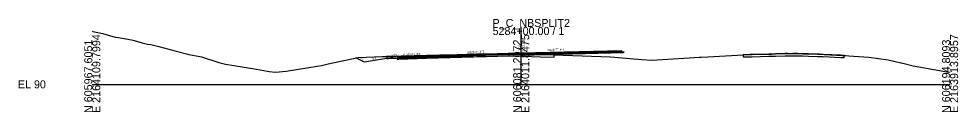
# Model space of a CAD drawing. Extents: x -26 to 1303, y -10 to 12038.
# Drawn here: x -25.7 to 302.8, y 2490.3 to 2522.8 of the extents above; entities that cross this region are included whole.
import ezdxf

# ---------------------------------------------------------------- set-up
doc = ezdxf.new("R2010")
doc.units = 0
for name, color, linetype in [('RD_GPK_XS_Cell', 7, 'Continuous'), ('RD_XS_Base', 7, 'Continuous'), ('RD_XS_ExGround', 7, 'Continuous'), ('RD_XS_ExPaveRet', 7, 'Continuous'), ('RD_XS_Greenside', 7, 'Continuous'), ('RD_XS_Pave', 7, 'Continuous'), ('RD_XS_PaveOvlay_CP', 7, 'Continuous'), ('RD_XS_TieSlope', 7, 'Continuous'), ('RD_XS_TX_Elev_EX', 7, 'Continuous'), ('RD_XS_TX_Elev_PR', 7, 'Continuous'), ('RD_XS_TX_ShdSlope', 7, 'Continuous'), ('RD_XS_TX_Slope', 7, 'Continuous')]:
    doc.layers.add(name, color=color, linetype=linetype)

msp = doc.modelspace()

# ---------------------------------------------------------------- linework, layer by layer
at = {"layer": 'RD_GPK_XS_Cell'}
for p, q in [((150, 2500), (150, 2520)), ((0, 2500), (150, 2500)), ((150, 2500), (300, 2500))]:
    msp.add_line(p, q, dxfattribs=at)
at = {"layer": 'RD_XS_Base'}
for p, q in [((150, 2510.51), (116.74, 2509.64)), ((116.74, 2509.14), (150, 2510.01)), ((138, 2510.2), (138, 2510.2)), ((150, 2510.51), (185.75, 2511.44)), ((185.75, 2510.94), (150, 2510.01)), ((150, 2510.01), (150, 2510.67)), ((150, 2510.67), (150, 2510.67)), ((150, 2510.67), (150, 2510.67)), ((150, 2510.67), (150, 2510.51)), ((150, 2510.51), (150, 2510.51)), ((150, 2510.01), (150, 2510.51)), ((150, 2510.51), (150, 2510.51)), ((150, 2510.51), (150, 2510.51)), ((150, 2510.01), (150, 2510.01)), ((174, 2511.13), (174, 2511.13)), ((174, 2511.13), (174, 2511.13)), ((174, 2510.63), (174, 2510.63)), ((174, 2510.63), (174, 2510.63)), ((185.25, 2511.43), (185.25, 2511.43)), ((185.75, 2511.44), (185.75, 2510.94)), ((185.75, 2511.41), (185.75, 2511.41)), ((107.17, 2509.26), (106.67, 2509.24)), ((106.67, 2509.24), (106.67, 2509.24)), ((106.67, 2509.24), (106.67, 2508.74)), ((106.67, 2508.74), (107.17, 2508.76)), ((116.74, 2509.64), (107.17, 2509.26)), ((107.17, 2509.26), (107.17, 2509.26)), ((107.17, 2508.76), (116.74, 2509.14)), ((107.17, 2508.76), (107.17, 2508.76)), ((138, 2509.7), (138, 2509.7))]:
    msp.add_line(p, q, dxfattribs=at)
at = {"layer": 'RD_XS_ExGround'}
msp.add_lwpolyline([(0, 2518.55), (0.24, 2518.48), (3.71, 2517.69), (5.2, 2517.27), (8.05, 2516.5), (9.01, 2516.34), (10.51, 2516.09), (13.73, 2515.52), (14.69, 2515.34), (17.51, 2514.48), (19.27, 2513.99), (20.51, 2513.84), (23.27, 2513.17), (28.54, 2511.77), (29.39, 2511.55), (33.39, 2510.55), (33.83, 2510.45), (37.64, 2509.68), (38.2, 2509.55), (44.28, 2507.66), (46.61, 2507.04), (49.55, 2506.54), (57.48, 2505.27), (61.29, 2504.56), (61.86, 2504.49), (64.07, 2504.23), (67.77, 2504.65), (78.66, 2506.3), (80.21, 2506.61), (82.52, 2507.13), (92.95, 2509.42), (101.41, 2509.66), (102.88, 2509.71), (103.65, 2509.73), (121.42, 2510.21), (121.58, 2510.22), (121.59, 2510.22), (127.6, 2510.35), (134.37, 2510.47), (135.32, 2510.49), (137.76, 2510.5), (137.9, 2510.5), (145.56, 2510.71), (145.94, 2510.71), (147.33, 2510.67), (150.74, 2510.63), (156.76, 2510.39), (161.51, 2510.26), (168.08, 2510.04), (181.16, 2509.55), (182.76, 2509.49), (192.04, 2508.7), (195.74, 2508.41), (206.88, 2509.13), (212.32, 2509.5), (212.89, 2509.5), (215.29, 2509.61), (227.59, 2510.34), (230.78, 2510.4), (237.65, 2510.55), (238.91, 2510.59), (243.17, 2510.75), (243.35, 2510.7), (245.65, 2510.73), (246.55, 2510.71), (248.5, 2510.67), (253.69, 2510.5), (260.31, 2510.19), (261.75, 2510.13), (262.43, 2510.1), (262.96, 2510.08), (263.68, 2510.03), (264.6, 2509.97), (271.54, 2509.5), (275, 2508.99), (278.3, 2508.52), (282.79, 2507.56), (283.06, 2507.5), (283.47, 2507.4), (287.12, 2506.48), (296.25, 2504.87), (299.47, 2504.29), (300, 2504.39)], dxfattribs=at)
at = {"layer": 'RD_XS_ExPaveRet'}
for points in [[(161.51, 2510.26), (161.51, 2510.26), (156.76, 2510.39), (156.76, 2510.39), (150.74, 2510.63), (147.33, 2510.67), (147.33, 2510.67), (145.94, 2510.71), (145.94, 2510.71), (145.94, 2510.71), (145.56, 2510.71), (145.56, 2510.71), (145.56, 2510.71), (145.56, 2510.71), (137.9, 2510.5), (137.9, 2510.5), (137.76, 2510.5), (135.32, 2510.49), (135.32, 2510.49), (134.37, 2510.47), (134.37, 2510.47), (127.6, 2510.35), (127.6, 2510.35), (127.6, 2510.35), (121.59, 2510.22), (121.59, 2510.22), (121.58, 2510.22), (121.42, 2510.21), (121.42, 2510.21), (103.65, 2509.73), (103.65, 2509.73), (102.88, 2509.71), (102.88, 2509.71), (102.88, 2508.96), (103.65, 2508.98), (103.65, 2508.98), (121.42, 2509.46), (121.42, 2509.46), (121.58, 2509.47), (121.59, 2509.47), (121.59, 2509.47), (127.6, 2509.6), (127.6, 2509.6), (127.6, 2509.6), (134.37, 2509.72), (134.37, 2509.72), (135.32, 2509.74), (135.32, 2509.74), (137.76, 2509.75), (137.9, 2509.75), (137.9, 2509.75), (145.56, 2509.96), (145.56, 2509.96), (145.56, 2509.96), (145.56, 2509.96), (145.94, 2509.96), (145.94, 2509.96), (145.94, 2509.96), (147.33, 2509.92), (147.33, 2509.92), (150.74, 2509.88), (156.76, 2509.64), (156.76, 2509.64), (161.51, 2509.51), (161.51, 2509.51), (161.51, 2509.51), (161.51, 2510.26), (161.51, 2510.26), (161.51, 2510.26)], [(161.51, 2510.26), (156.76, 2510.39), (150.74, 2510.63), (147.33, 2510.67), (145.94, 2510.71), (145.56, 2510.71), (137.9, 2510.5), (137.76, 2510.5), (135.32, 2510.49), (134.37, 2510.47), (127.6, 2510.35), (121.59, 2510.22), (121.58, 2510.22), (121.42, 2510.21), (103.65, 2509.73), (102.88, 2509.71), (102.88, 2508.96), (103.65, 2508.98), (121.42, 2509.46), (121.58, 2509.47), (121.59, 2509.47), (127.6, 2509.6), (134.37, 2509.72), (135.32, 2509.74), (137.76, 2509.75), (137.9, 2509.75), (145.56, 2509.96), (145.94, 2509.96), (147.33, 2509.92), (150.74, 2509.88), (156.76, 2509.64), (161.51, 2509.51), (161.51, 2510.26)], [(262.43, 2510.1), (261.75, 2510.13), (255.6, 2510.41), (254.24, 2510.47), (253.69, 2510.5), (250.46, 2510.6), (248.5, 2510.67), (246.66, 2510.71), (246.55, 2510.71), (245.7, 2510.73), (245.65, 2510.73), (245, 2510.72), (243.35, 2510.7), (243.21, 2510.74), (243.17, 2510.75), (242.32, 2510.72), (238.91, 2510.59), (238.49, 2510.58), (237.65, 2510.55), (236.57, 2510.53), (230.78, 2510.4), (230.05, 2510.39), (227.59, 2510.34), (227.59, 2510.34), (227.59, 2510.34), (227.59, 2510.23), (227.59, 2509.59), (227.59, 2509.59), (227.59, 2509.59), (230.05, 2509.64), (230.78, 2509.65), (236.57, 2509.78), (237.65, 2509.8), (238.49, 2509.83), (238.91, 2509.84), (242.32, 2509.97), (243.17, 2510), (243.21, 2509.99), (243.35, 2509.95), (245, 2509.97), (245.65, 2509.98), (245.7, 2509.98), (246.55, 2509.96), (246.66, 2509.96), (248.5, 2509.92), (250.46, 2509.85), (253.69, 2509.75), (254.24, 2509.72), (255.6, 2509.66), (261.75, 2509.38), (262.43, 2509.35), (262.96, 2509.33), (262.96, 2509.33), (262.96, 2509.81), (262.96, 2510.08), (262.96, 2510.08), (262.43, 2510.1)], [(262.43, 2510.1), (261.75, 2510.13), (255.6, 2510.41), (254.24, 2510.47), (253.69, 2510.5), (250.46, 2510.6), (248.5, 2510.67), (246.66, 2510.71), (246.55, 2510.71), (245.7, 2510.73), (245.65, 2510.73), (245, 2510.72), (243.35, 2510.7), (243.21, 2510.74), (243.17, 2510.75), (242.32, 2510.72), (238.91, 2510.59), (238.49, 2510.58), (237.65, 2510.55), (236.57, 2510.53), (230.78, 2510.4), (230.05, 2510.39), (227.59, 2510.34), (227.59, 2510.34), (227.59, 2510.23), (227.59, 2509.59), (227.59, 2509.59), (230.05, 2509.64), (230.78, 2509.65), (236.57, 2509.78), (237.65, 2509.8), (238.49, 2509.83), (238.91, 2509.84), (242.32, 2509.97), (243.17, 2510), (243.21, 2509.99), (243.35, 2509.95), (245, 2509.97), (245.65, 2509.98), (245.7, 2509.98), (246.55, 2509.96), (246.66, 2509.96), (248.5, 2509.92), (250.46, 2509.85), (253.69, 2509.75), (254.24, 2509.72), (255.6, 2509.66), (261.75, 2509.38), (262.43, 2509.35), (262.96, 2509.33), (262.96, 2509.81), (262.96, 2510.08), (262.43, 2510.1)]]:
    msp.add_lwpolyline(points, dxfattribs=at)
at = {"layer": 'RD_XS_Greenside'}
for p, q in [((95.17, 2507.75), (92.18, 2509.25)), ((105.17, 2509.42), (95.17, 2507.75))]:
    msp.add_line(p, q, dxfattribs=at)
at = {"layer": 'RD_XS_Pave'}
for p, q in [((150, 2510.83), (116.74, 2509.96)), ((116.74, 2509.8), (150, 2510.67)), ((150, 2510.67), (116.74, 2509.8)), ((116.74, 2509.64), (150, 2510.51)), ((138, 2510.52), (138, 2510.52)), ((138, 2510.36), (138, 2510.36)), ((138, 2510.36), (138, 2510.36)), ((138, 2510.2), (138, 2510.2)), ((185.25, 2511.74), (150, 2510.83)), ((185.25, 2511.59), (150, 2510.67)), ((150, 2510.67), (185.25, 2511.59)), ((150, 2510.51), (185.25, 2511.43)), ((150, 2510.83), (150, 2510.83)), ((150, 2510.67), (150, 2510.67)), ((150, 2510.67), (150, 2510.67)), ((150, 2510.67), (150, 2510.51)), ((150, 2510.67), (150, 2510.67)), ((150, 2510.51), (150, 2510.67)), ((150, 2510.67), (150, 2510.67)), ((150, 2510.67), (150, 2510.67)), ((150, 2510.51), (150, 2510.51)), ((150, 2510.51), (150, 2510.51)), ((174, 2511.45), (174, 2511.45)), ((174, 2511.45), (174, 2511.45)), ((174, 2511.29), (174, 2511.29)), ((174, 2511.29), (174, 2511.29)), ((174, 2511.29), (174, 2511.29)), ((174, 2511.29), (174, 2511.29)), ((174, 2511.13), (174, 2511.13)), ((174, 2511.13), (174, 2511.13)), ((185.25, 2511.59), (185.25, 2511.74)), ((185.25, 2511.74), (185.25, 2511.74)), ((185.25, 2511.43), (185.25, 2511.59)), ((185.25, 2511.59), (185.25, 2511.59)), ((116.74, 2509.96), (107.17, 2509.58)), ((107.17, 2509.42), (116.74, 2509.8)), ((116.74, 2509.8), (107.17, 2509.42)), ((107.17, 2509.26), (116.74, 2509.64)), ((107.17, 2509.58), (107.17, 2509.58)), ((107.17, 2509.58), (107.17, 2509.42)), ((107.17, 2509.42), (107.17, 2509.42)), ((107.17, 2509.42), (107.17, 2509.26))]:
    msp.add_line(p, q, dxfattribs=at)
at = {"layer": 'RD_XS_PaveOvlay_CP'}
for p, q in [((150, 2510.83), (116.74, 2509.96)), ((138, 2510.52), (138, 2510.52)), ((185.25, 2511.74), (150, 2510.83)), ((150, 2510.83), (150, 2510.83)), ((174, 2511.45), (174, 2511.45)), ((174, 2511.45), (174, 2511.45)), ((116.74, 2509.96), (107.17, 2509.58))]:
    msp.add_line(p, q, dxfattribs=at)
at = {"layer": 'RD_XS_TieSlope'}
msp.add_line((107.17, 2509.58), (105.17, 2509.42), dxfattribs=at)

# ---------------------------------------------------------------- texts
at = {"layer": 'RD_GPK_XS_Cell'}
for s, p in [('5284+00.00 / 1', (140, 2517.2)), ('P_C_NBSPLIT2', (140, 2520)), ('EL 90', (-26, 2498.6))]:
    msp.add_text(s, height=2.8, dxfattribs=at).set_placement(p)
for s, p in [('E 2164109.7994', (2.8, 2490)), ('E 2164011.8475', (152.8, 2490)), ('E 2163913.8957', (302.8, 2490)), ('N 605967.6051', (0, 2490)), ('N 606081.2072', (150, 2490)), ('N 606194.8093', (300, 2490))]:
    msp.add_text(s, height=2.8, rotation=90, dxfattribs=at).set_placement(p)
at = {"layer": 'RD_XS_TX_Elev_EX'}
msp.add_text('100.64', height=0.6, rotation=90, dxfattribs=at).set_placement((149.74, 2511.61))
at = {"layer": 'RD_XS_TX_Elev_PR'}
msp.add_text('100.83', height=1, rotation=90, dxfattribs=at).set_placement((151.25, 2511.3))
at = {"layer": 'RD_XS_TX_ShdSlope'}
msp.add_text('12.5:1', height=0.75, rotation=4.5739, dxfattribs=at).set_placement((104.7, 2509.66))
at = {"layer": 'RD_XS_TX_Slope'}
for s, rotation, p in [('0.040 FT./FT.', 2.2906, (108.79, 2509.95)), ('0.028 FT./FT.', 1.6039, (131.09, 2510.8)), ('0.028 FT./FT.', 1.6039, (159.06, 2511.58)), ('2:1', 333.4349, (93.42, 2508.8)), ('6:1', 9.4642, (98.1, 2508.45))]:
    msp.add_text(s, height=0.75, rotation=rotation, dxfattribs=at).set_placement(p)

doc.saveas('drawing.dxf')
